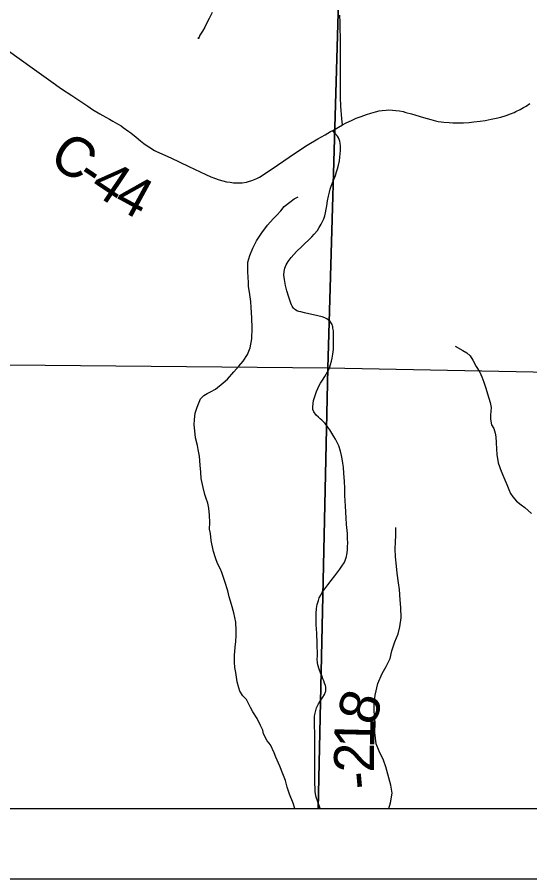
# Model space of a CAD drawing. Extents: x -7.1 to 34, y 0 to 22.
# Drawn here: x 5.186 to 5.914, y 14 to 15.224 of the extents above; entities that cross this region are included whole.
import ezdxf

# ---------------------------------------------------------------- set-up
doc = ezdxf.new("R2010")
doc.units = 0
for name, color, linetype in [('GM_X_County_Road', 7, 'Continuous'), ('GM_X_County_Road_Text', 7, 'Continuous'), ('GM_X_Minor_River', 7, 'Continuous'), ('GM_X_Section', 7, 'Continuous'), ('GM_X_Township_Road', 7, 'Continuous'), ('GM_X_Township_Road_Text', 7, 'Continuous'), ('GM_X_Unincorporated', 7, 'Continuous'), ('SH_Cut_Line', 7, 'Continuous'), ('SH_Data', 7, 'Continuous')]:
    doc.layers.add(name, color=color, linetype=linetype)

msp = doc.modelspace()

# ---------------------------------------------------------------- linework, layer by layer
at = {"layer": 'GM_X_County_Road'}
msp.add_line((5.6343, 15.0632), (5.6483, 15.0714), dxfattribs=at)
for points in [[(5.1735, 15.1765), (5.2071, 15.1522), (5.2339, 15.1331), (5.2491, 15.1226), (5.2635, 15.1129), (5.2862, 15.0976), (5.2929, 15.0932), (5.3035, 15.0869), (5.312, 15.0821), (5.3174, 15.0791), (5.3219, 15.0764), (5.3286, 15.0726), (5.3336, 15.0697), (5.3368, 15.0676), (5.3447, 15.062), (5.3473, 15.06), (5.3549, 15.0538), (5.3611, 15.0487), (5.3659, 15.0447), (5.3695, 15.0422), (5.3732, 15.0398), (5.3812, 15.0349), (5.3838, 15.0336), (5.4043, 15.0242), (5.4298, 15.0121), (5.4539, 15.0005), (5.4612, 14.9972), (5.4663, 14.9953), (5.473, 14.9931), (5.4782, 14.9917), (5.4833, 14.9905), (5.4886, 14.9896), (5.4934, 14.989), (5.4977, 14.9888), (5.5055, 14.989), (5.5117, 14.9899), (5.5148, 14.9906), (5.5196, 14.992), (5.5219, 14.9929), (5.5266, 14.995), (5.5304, 14.997), (5.5329, 14.9984), (5.5561, 15.0141), (5.5815, 15.0314), (5.5981, 15.0422), (5.6132, 15.0514), (5.6234, 15.0573), (5.6314, 15.0616), (5.6343, 15.0632)], [(5.6483, 15.0714), (5.6533, 15.0739), (5.6608, 15.0776), (5.6674, 15.0806), (5.6746, 15.0833), (5.6825, 15.086), (5.6885, 15.0879), (5.695, 15.0897), (5.7003, 15.091), (5.7047, 15.0916), (5.7102, 15.0922), (5.714, 15.0924), (5.7192, 15.0922), (5.7241, 15.0918), (5.7291, 15.091), (5.7342, 15.09), (5.7382, 15.089), (5.7464, 15.0868), (5.7631, 15.0817), (5.7736, 15.0787), (5.7768, 15.078), (5.7805, 15.0771), (5.7841, 15.0762), (5.7886, 15.0756), (5.7924, 15.0751), (5.7997, 15.0745), (5.8052, 15.0743), (5.8139, 15.0742), (5.8203, 15.0743), (5.8281, 15.0747), (5.8348, 15.0753), (5.8437, 15.0763), (5.8509, 15.0774), (5.8596, 15.0791), (5.8665, 15.0806), (5.8731, 15.0824), (5.8806, 15.0847), (5.8867, 15.0868), (5.8919, 15.0888), (5.8945, 15.09), (5.9008, 15.0932), (5.9056, 15.0959), (5.9091, 15.098), (5.9144, 15.1016)]]:
    msp.add_lwpolyline(points, dxfattribs=at)
at = {"layer": 'GM_X_Minor_River'}
for points in [[(5.4629, 15.2307), (5.4589, 15.2226), (5.4552, 15.2153), (5.4526, 15.21), (5.4493, 15.2042), (5.4456, 15.1988), (5.4434, 15.1935), (5.4437, 15.1954)], [(5.5196, 14.7972), (5.5183, 14.8116), (5.5178, 14.8204), (5.5165, 14.8303), (5.5148, 14.842), (5.5147, 14.8474), (5.5142, 14.855), (5.5137, 14.8622), (5.5136, 14.8691), (5.5139, 14.8763), (5.5164, 14.8858), (5.5208, 14.8962), (5.526, 14.9065), (5.5334, 14.9177), (5.5415, 14.9288), (5.5497, 14.9377), (5.5546, 14.9424), (5.5605, 14.9493), (5.5654, 14.9551), (5.5732, 14.9613), (5.5796, 14.9663), (5.5852, 14.9691)], [(5.5807, 14.1), (5.5781, 14.1072), (5.573, 14.1201), (5.5695, 14.1303), (5.5671, 14.1394), (5.5635, 14.1493), (5.5592, 14.1599), (5.5537, 14.1727), (5.5513, 14.1788), (5.5459, 14.1905), (5.5412, 14.1961), (5.5362, 14.206), (5.535, 14.2113), (5.5318, 14.2177), (5.5268, 14.2279), (5.521, 14.2373), (5.5175, 14.2434), (5.5116, 14.2547), (5.5066, 14.26), (5.5024, 14.2664), (5.5008, 14.2713), (5.4988, 14.2796), (5.4967, 14.2933), (5.4954, 14.3001), (5.4949, 14.3077), (5.4948, 14.3173), (5.4958, 14.3291), (5.4968, 14.3371), (5.497, 14.3458), (5.4973, 14.3527), (5.4968, 14.3645), (5.4939, 14.3781), (5.4907, 14.3895), (5.4872, 14.4005), (5.4851, 14.4092), (5.4812, 14.4225), (5.4768, 14.4354), (5.4745, 14.4407), (5.4706, 14.4478), (5.4678, 14.4562), (5.465, 14.4649), (5.4626, 14.4759), (5.4618, 14.4808), (5.4605, 14.4907), (5.4592, 14.4968), (5.4599, 14.5063), (5.4593, 14.5166), (5.4581, 14.5268), (5.4568, 14.5337), (5.4545, 14.5401), (5.4528, 14.5462), (5.4504, 14.556), (5.4476, 14.5689), (5.4471, 14.5777), (5.4462, 14.5875), (5.4449, 14.6005), (5.4432, 14.61), (5.442, 14.6156), (5.4396, 14.6263), (5.4383, 14.6365), (5.4374, 14.6449), (5.438, 14.6525), (5.439, 14.6617), (5.4416, 14.6701), (5.4463, 14.6819), (5.4512, 14.6866), (5.4561, 14.6897), (5.4609, 14.6917), (5.4677, 14.6956), (5.4789, 14.7045), (5.4849, 14.7099), (5.4938, 14.7203), (5.5009, 14.7284), (5.5072, 14.7357), (5.5132, 14.745), (5.5172, 14.7542), (5.5193, 14.7671), (5.5198, 14.7824), (5.5196, 14.7972)], [(5.8083, 14.7566), (5.8194, 14.7507), (5.8247, 14.7473), (5.8297, 14.7432), (5.8336, 14.7368), (5.8383, 14.7277), (5.8433, 14.7198), (5.846, 14.7134), (5.8492, 14.7054), (5.852, 14.6971), (5.8543, 14.6891), (5.8559, 14.6827), (5.8579, 14.6766), (5.8592, 14.6698), (5.8589, 14.6641), (5.8586, 14.6591), (5.8587, 14.653), (5.8599, 14.6451), (5.863, 14.6398), (5.865, 14.6333), (5.8662, 14.628), (5.8667, 14.62), (5.8668, 14.6105), (5.8673, 14.6029), (5.8694, 14.5912), (5.8734, 14.5794), (5.8773, 14.5703), (5.8816, 14.5601), (5.8843, 14.5533), (5.8867, 14.5476), (5.8902, 14.5428), (5.8952, 14.5364), (5.9021, 14.5315), (5.9071, 14.5274), (5.9166, 14.5188)], [(5.714, 14.1), (5.7164, 14.1078), (5.7187, 14.1215), (5.7171, 14.1328), (5.7125, 14.1484), (5.7099, 14.1591), (5.7064, 14.1686), (5.7003, 14.1815), (5.6961, 14.1917), (5.6942, 14.2077), (5.6945, 14.2217), (5.6934, 14.2381), (5.693, 14.2479), (5.6945, 14.2608), (5.6983, 14.2776), (5.7044, 14.2916), (5.7101, 14.3015), (5.7158, 14.3132), (5.7184, 14.3239), (5.7226, 14.3368), (5.7272, 14.3482), (5.7298, 14.3581), (5.7317, 14.3706), (5.731, 14.3854), (5.7302, 14.3964), (5.729, 14.4108), (5.7279, 14.4203), (5.7259, 14.4344), (5.7248, 14.4443), (5.7236, 14.4576), (5.7232, 14.469), (5.7236, 14.4784), (5.724, 14.4883), (5.724, 14.4993)]]:
    msp.add_lwpolyline(points, dxfattribs=at)
at = {"layer": 'GM_X_Section'}
for points in [[(5.6569, 15.7356), (5.6272, 14.7254), (4.6234, 14.7351), (4.645, 15.7523)], [(6.6705, 15.7268), (6.6482, 14.7054), (5.6272, 14.7254), (5.6569, 15.7356)]]:
    msp.add_lwpolyline(points, close=True, dxfattribs=at)
at = {"layer": 'GM_X_Township_Road'}
msp.add_line((5.6343, 15.0632), (5.6483, 15.0714), dxfattribs=at)
for points in [[(2.1, 17.7253), (2.1, 14.1), (6.633, 14.1), (6.6565, 15.1357), (6.6586, 15.2372), (6.6748, 15.9993), (6.6822, 16.3488), (6.7058, 17.2839), (6.7118, 17.7486)], [(5.6483, 15.0714), (5.6475, 15.0798), (5.6459, 15.098), (5.6457, 15.1015), (5.6456, 15.1064), (5.6454, 15.1957), (5.645, 15.207), (5.6447, 15.2165), (5.6446, 15.2272)], [(5.6164, 14.1), (5.6154, 14.1026), (5.613, 14.1093), (5.6109, 14.116), (5.6099, 14.1205), (5.6095, 14.1241), (5.6092, 14.1294), (5.6089, 14.1344), (5.6088, 14.1411), (5.6087, 14.1519), (5.6089, 14.169), (5.6091, 14.1868), (5.6087, 14.2039), (5.6082, 14.2201), (5.6084, 14.2259), (5.6085, 14.2304), (5.6091, 14.2336), (5.6099, 14.2373), (5.6115, 14.2431), (5.6143, 14.2486), (5.6176, 14.254), (5.6205, 14.2582), (5.6226, 14.262), (5.6242, 14.2654), (5.6245, 14.2667), (5.6247, 14.2686), (5.6246, 14.2705), (5.6244, 14.2722), (5.6241, 14.2747), (5.6228, 14.2777), (5.6215, 14.2812), (5.6203, 14.2842), (5.6191, 14.2874), (5.6168, 14.2928), (5.615, 14.2979), (5.6131, 14.3042), (5.6128, 14.3071), (5.6124, 14.3121), (5.6125, 14.3169), (5.6124, 14.3348), (5.6119, 14.3486), (5.6114, 14.3552), (5.6109, 14.3609), (5.6107, 14.37), (5.6108, 14.377), (5.6114, 14.3838), (5.6124, 14.3897), (5.6139, 14.3952), (5.6153, 14.3993), (5.6172, 14.403), (5.6194, 14.4071), (5.623, 14.412), (5.6274, 14.4175), (5.6319, 14.4238), (5.6373, 14.4303), (5.6431, 14.4381), (5.6445, 14.4399), (5.6473, 14.444), (5.6504, 14.449), (5.652, 14.4523), (5.653, 14.4551), (5.6538, 14.458), (5.6543, 14.4607), (5.6547, 14.4631), (5.6551, 14.4672), (5.6555, 14.4716), (5.6556, 14.4772), (5.6555, 14.4832), (5.6551, 14.4905), (5.6541, 14.5034), (5.6533, 14.5128), (5.6523, 14.5296), (5.6517, 14.5447), (5.6514, 14.5545), (5.651, 14.5651), (5.6502, 14.5758), (5.6496, 14.5849), (5.6488, 14.5904), (5.6477, 14.5969), (5.6468, 14.6014), (5.6453, 14.6078), (5.6428, 14.615), (5.6407, 14.6199), (5.6382, 14.6244), (5.6358, 14.6284), (5.6301, 14.6377), (5.6274, 14.6418), (5.6234, 14.6468), (5.6211, 14.6492), (5.6189, 14.6514), (5.6165, 14.6533), (5.6139, 14.6557), (5.6107, 14.6589), (5.6074, 14.6634), (5.6062, 14.6669), (5.606, 14.6705), (5.6069, 14.6796), (5.6097, 14.688), (5.6115, 14.6923), (5.6153, 14.7008), (5.617, 14.7042), (5.6197, 14.7086), (5.6233, 14.7139), (5.6268, 14.7202), (5.6287, 14.7238), (5.6303, 14.7273), (5.6314, 14.7306), (5.6327, 14.7353), (5.6335, 14.7397), (5.6345, 14.7454), (5.6352, 14.752), (5.6355, 14.7584), (5.6356, 14.7694), (5.6355, 14.7742), (5.6352, 14.7784), (5.6347, 14.7822), (5.6344, 14.7842), (5.6341, 14.7858), (5.6335, 14.7875), (5.6327, 14.7888), (5.6318, 14.7904), (5.6307, 14.7918), (5.6284, 14.7938), (5.6258, 14.7955), (5.623, 14.7969), (5.6192, 14.7983), (5.6134, 14.7999), (5.6071, 14.8012), (5.6004, 14.8027), (5.5942, 14.804), (5.5888, 14.8054), (5.5861, 14.8061), (5.5835, 14.8071), (5.5815, 14.8082), (5.5801, 14.8095), (5.5788, 14.8107), (5.5776, 14.8123), (5.5766, 14.8137), (5.5757, 14.8157), (5.5749, 14.818), (5.5733, 14.8223), (5.572, 14.8266), (5.5693, 14.8355), (5.5673, 14.8431), (5.5657, 14.8515), (5.5651, 14.8577), (5.5653, 14.8631), (5.5662, 14.8674), (5.568, 14.8722), (5.571, 14.8772), (5.5751, 14.8828), (5.5828, 14.8912), (5.5903, 14.8982), (5.6048, 14.9123), (5.608, 14.9158), (5.6125, 14.9213), (5.615, 14.9253), (5.6177, 14.9299), (5.6202, 14.9349), (5.6215, 14.9377), (5.623, 14.9419), (5.6242, 14.946), (5.6252, 14.9514), (5.6258, 14.956), (5.6268, 14.9632), (5.6282, 14.9699), (5.6296, 14.9758), (5.6308, 14.9799), (5.6323, 14.9843), (5.6341, 14.989), (5.6381, 14.9993), (5.6398, 15.0043), (5.6413, 15.0089), (5.6426, 15.0138), (5.6438, 15.0201), (5.6445, 15.0254), (5.645, 15.0302), (5.6453, 15.0346), (5.6452, 15.0415), (5.6448, 15.045), (5.6442, 15.0479), (5.6434, 15.0505), (5.6423, 15.0529), (5.6409, 15.0552), (5.6374, 15.0596), (5.6355, 15.0618), (5.6343, 15.0632)]]:
    msp.add_lwpolyline(points, dxfattribs=at)
at = {"layer": 'GM_X_Unincorporated'}
for points in [[(4.6065, 14.1), (5.6136, 14.1), (5.6272, 14.7254), (4.6234, 14.7351)], [(5.6136, 14.1), (6.6341, 14.1), (6.6482, 14.7054), (5.6272, 14.7254)]]:
    msp.add_lwpolyline(points, close=True, dxfattribs=at)
at = {"layer": 'SH_Cut_Line'}
msp.add_lwpolyline([(2.1, 17.7253), (2.1, 14.1), (8.9, 14.1), (8.9, 17.7079), (8.6668, 17.7136), (8.4472, 17.7189), (7.7202, 17.7285), (6.7118, 17.7486), (6.3575, 17.7557), (6.1904, 17.7592), (5.7514, 17.7685), (5.5047, 17.7737), (5.1115, 17.7819), (5.0544, 17.7831), (5.0443, 17.7832), (4.7094, 17.7848), (4.5657, 17.7857), (4.3, 17.7873), (3.8304, 17.7952), (3.8238, 17.6717), (3.7215, 17.6707), (3.0659, 17.6986), (2.7886, 17.7105), (2.5551, 17.7155)], close=True, dxfattribs=at)
at = {"layer": 'SH_Data'}
for p, q in [((2.1, 14.1), (8.9, 14.1)), ((2, 14), (9, 14))]:
    msp.add_line(p, q, dxfattribs=at)

# ---------------------------------------------------------------- texts
at = {"layer": 'GM_X_County_Road_Text'}
for s, rotation, p in [('C', 325.8163, (5.2286, 15.0182)), ('-', 325.8702, (5.2673, 14.9919)), ('4', 326.0756, (5.2868, 14.9787)), ('4', 331.4263, (5.3208, 14.9562))]:
    msp.add_text(s, height=0.0568, rotation=rotation, dxfattribs=at).set_placement(p)
at = {"layer": 'GM_X_Township_Road_Text'}
for s, rotation, p in [('8', 71.9225, (5.6931, 14.2157)), ('1', 88.678, (5.6931, 14.1853)), ('2', 89.7378, (5.6929, 14.1509)), ('-', 95.1211, (5.6949, 14.1293))]:
    msp.add_text(s, height=0.0568, rotation=rotation, dxfattribs=at).set_placement(p)

doc.saveas('drawing.dxf')
